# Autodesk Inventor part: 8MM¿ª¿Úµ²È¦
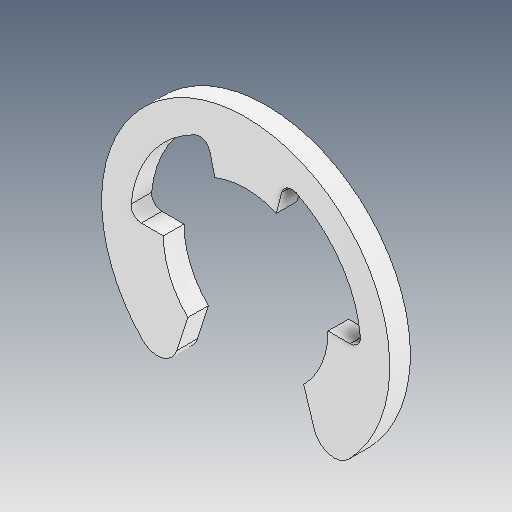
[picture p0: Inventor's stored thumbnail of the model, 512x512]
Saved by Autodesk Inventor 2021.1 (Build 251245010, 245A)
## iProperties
Created: 2021-05
Part Number: 8MM¿ª¿Úµ²È¦
Material: Ogólny
Document SubType Name: Modeling
Designer: user
Density: 1 g/cm^3
Appearance: Domyślna
Author: user
Revision Number: ÈÎºÎ
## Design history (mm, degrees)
feature "ÊäÈë1"
node "Bryła1"
